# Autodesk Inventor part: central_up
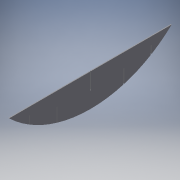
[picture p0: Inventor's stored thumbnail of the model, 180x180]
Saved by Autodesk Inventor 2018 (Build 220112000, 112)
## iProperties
Created: 2019-03
Part Number: central_up
Material: Generic
Document SubType Name: Modeling
Designer: vpimentel
Density: 1 g/cm^3
Appearance: Default
Author: vpimentel
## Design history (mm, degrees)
sketch "Sketch1"
  geometry: L1 (-1.45, -54.997)-(1.45, -54.997); L2 (0, 0)-(0, -110); L3 (-111.45, -47.108)-(-111.45, -94.108); L4 (-114.35, -47.108)-(-111.45, -47.108); L5 (111.45, -47.108)-(114.35, -47.108); L6 (111.45, -94.108)-(111.45, -47.108); L7 (114.35, -47.108)-(114.35, -93.252); L8 (204.35, -53.657)-(204.35, -25.657); L9 (204.35, -25.657)-(207.25, -25.657); L10 (207.25, -25.657)-(207.25, -51.91); L11 (-114.35, -93.252)-(-114.35, -47.108); L12 (-204.35, -25.657)-(-204.35, -53.657); L13 (-207.25, -25.657)-(-204.35, -25.657); L14 (-207.25, -51.91)-(-207.25, -25.657); L15 (-1.45, -54.997)-(1.45, -54.997); L16 (1.45, -54.997)-(1.45, 0); L17 (-1.45, 0)-(-1.45, -54.997); L18 (275, 0)-(1.45, 0); L19 (-1.45, 0)-(-275, 0); A1 r 398.75 centre (0, 288.75) between (0, -110) and (111.45, -94.108); A2 r 398.75 centre (0, 288.75) between (-111.45, -94.108) and (-1.45, -109.997); A3 r 398.75 centre (0, 288.75) between (114.35, -93.252) and (204.35, -53.657); A4 r 398.75 centre (0, 288.75) between (207.25, -51.91) and (275, 0); A5 r 398.75 centre (0, 288.75) between (-204.35, -53.657) and (-114.35, -93.252); A6 r 398.75 centre (0, 288.75) between (-275, 0) and (-207.25, -51.91); A7 r 123.752 centre (-0.5, 13.751) between (-1.45, -109.997) and (0, -110); 3 further points
  constraints: 38 end point, 14 point on circle, 7 centre point, 7 parallel, 3 horizontal, 3 point on line, 1 coincident, 1 midpoint, 1 perpendicular, 1 vertical
  dimensions: "d0" = 550 distance of L18.start L19.end; "d1" = 110 distance of L2.start L2.end; "d3" = 55 distance of A2.end L1.start; "d5" = 47 distance of L6.start L5.start; "d6" = 90 distance between parallel lines of L8 L7; "d7" = 28 distance of L8.start L8.end; "d9" = 2.9 distance between parallel lines of L10 L8 (= d12); "d10" = 2.9 distance between parallel lines of L11 L3 (= d12); "d11" = 2.9 distance between parallel lines of L14 L12 (= d12); "d12" = 2.9 distance between parallel lines of L17 L16; "d15" = 2.9 distance between parallel lines of L7 L6 (= d12)
extrude "Extrusion1" new body sketch "Sketch1" distance "d13" = 2.9 (= d10); taper "d14" = 0 deg
body "Solid1"
other parameters: "d2" = 2.9
